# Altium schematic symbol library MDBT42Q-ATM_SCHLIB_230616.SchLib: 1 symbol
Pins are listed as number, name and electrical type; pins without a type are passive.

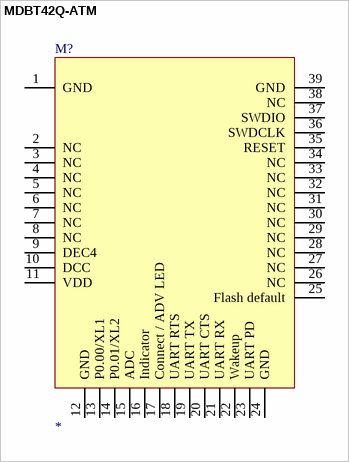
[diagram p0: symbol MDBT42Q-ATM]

## MDBT42Q-ATM
designator M?
MDBT42Q(52832_52810_52811)
pins: 1 GND, 2 NC, 3 NC, 4 NC, 5 NC, 6 NC, 7 NC, 8 NC, 9 DEC4, 10 DCC, 11 VDD, 12 GND, 13 P0.00/XL1, 14 P0.01/XL2, 15 ADC, 16 Indicator, 17 Connect / ADV LED, 18 UART RTS, 19 UART TX, 20 UART CTS, 21 UART RX, 22 Wakeup, 23 UART PD, 24 GND, 25 Flash default, 26 NC, 27 NC, 28 NC, 29 NC, 30 NC, 31 NC, 32 NC, 33 NC, 34 NC, 35 RESET, 36 SWDCLK, 37 SWDIO, 38 NC, 39 GND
